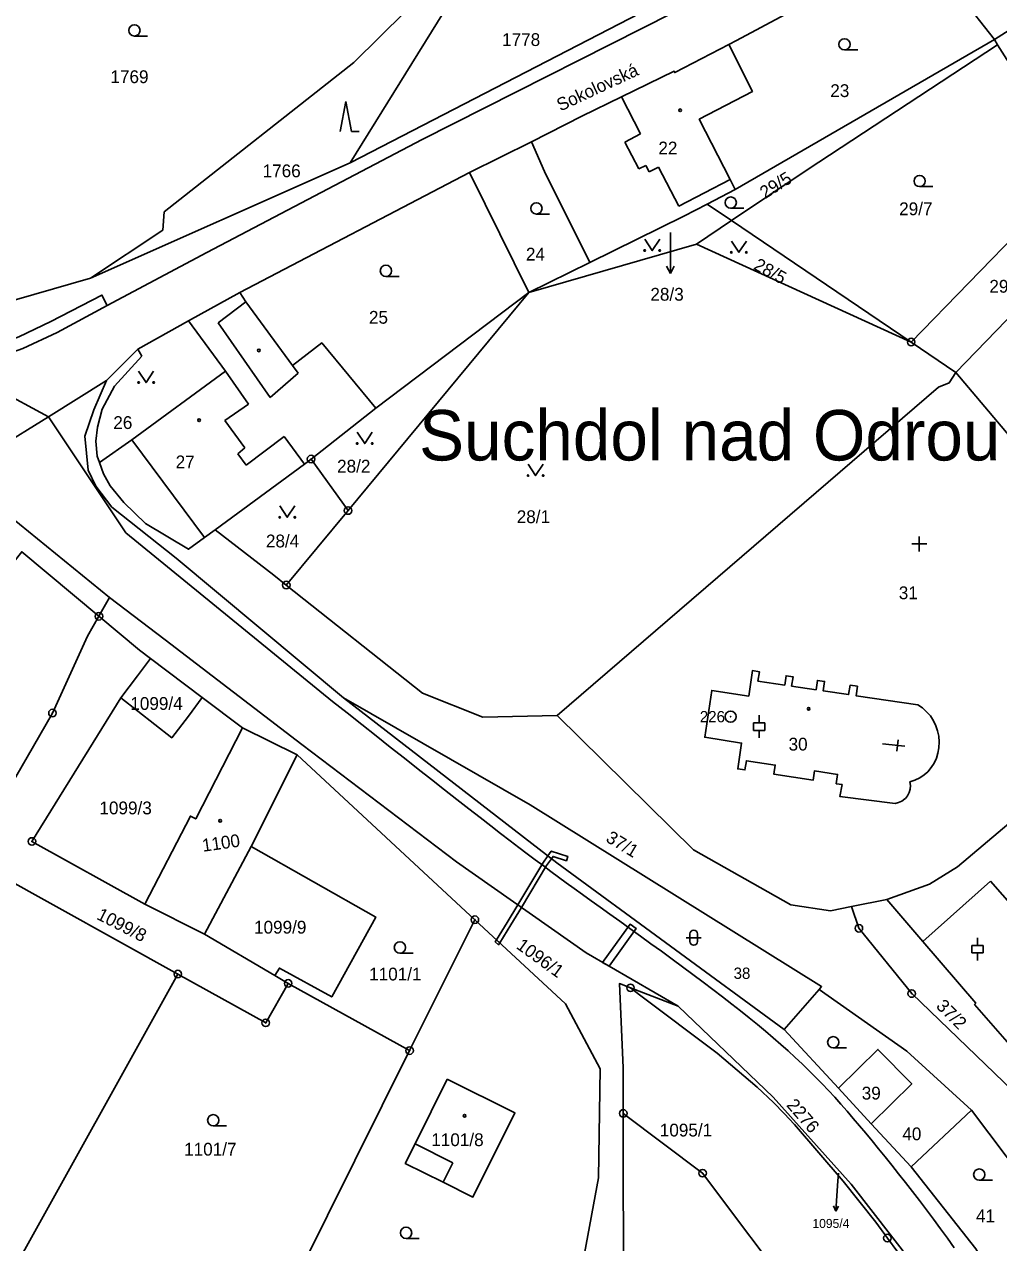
# Model space of a CAD drawing. Extents: x -504988 to -494607, y -1123820 to -1114018.
# Drawn here: x -497790.5 to -497661.1, y -1119332.3 to -1119170.5 of the extents above; entities that cross this region are included whole.
import ezdxf

# ---------------------------------------------------------------- set-up
doc = ezdxf.new("R2010")
doc.units = 0
for name, color, linetype in [('Hranice parcel', 7, 'Continuous'), ('Parcelní čísla', 7, 'Continuous'), ('Pop  PČ popisy', 7, 'Continuous'), ('Vnitřní kresba', 7, 'Continuous'), ('Věcná břemena k části', 7, 'Continuous'), ('Značky bodu BP', 7, 'Continuous'), ('Značky budov', 7, 'Continuous'), ('Značky kultur', 7, 'Continuous')]:
    doc.layers.add(name, color=color, linetype=linetype)

msp = doc.modelspace()

# ---------------------------------------------------------------- linework, layer by layer
at = {"layer": 'Hranice parcel'}
for p, q in [((-497661.69, -1119172.47), (-497620.57, -1119146.31)), ((-497696.9, -1119162.82), (-497747.25, -1119188.87)), ((-497668.67, -1119163.56), (-497661.69, -1119172.47)), ((-497747.25, -1119188.87), (-497734.84, -1119168.91)), ((-497696.1, -1119192.42), (-497661.69, -1119172.47)), ((-497661.69, -1119172.47), (-497661.25, -1119173.18)), ((-497723.18, -1119186.07), (-497731.4, -1119190.16)), ((-497747.25, -1119188.87), (-497781.75, -1119204.19)), ((-497761.89, -1119206.09), (-497731.4, -1119190.16)), ((-497651.17, -1119190.47), (-497672.74, -1119212.67)), ((-497699.82, -1119194.35), (-497696.1, -1119192.42)), ((-497696.58, -1119196.54), (-497699.82, -1119194.35)), ((-497701.23, -1119199.67), (-497696.58, -1119196.54)), ((-497696.58, -1119196.54), (-497672.74, -1119212.67)), ((-497701.23, -1119199.67), (-497723.5, -1119206.09)), ((-497672.74, -1119212.67), (-497701.23, -1119199.67)), ((-497650.53, -1119199.84), (-497666.81, -1119216.69)), ((-497723.5, -1119206.09), (-497715.43, -1119202.11)), ((-497781.75, -1119204.19), (-497796.95, -1119208.58)), ((-497768.72, -1119209.86), (-497761.89, -1119206.09)), ((-497723.5, -1119206.09), (-497747.52, -1119235.04)), ((-497743.85, -1119221.44), (-497723.5, -1119206.09)), ((-497775.46, -1119213.63), (-497768.72, -1119209.86)), ((-497666.81, -1119216.69), (-497672.74, -1119212.67)), ((-497779.6, -1119217.79), (-497775.46, -1119213.63)), ((-497775.46, -1119213.63), (-497774.9, -1119214.56)), ((-497801.27, -1119215.06), (-497787.31, -1119222.58)), ((-497779.6, -1119217.79), (-497787.31, -1119222.58)), ((-497666.81, -1119216.69), (-497635.22, -1119254.15)), ((-497787.31, -1119222.58), (-497799.78, -1119230.32)), ((-497752.44, -1119228.2), (-497743.85, -1119221.44)), ((-497752.44, -1119228.2), (-497747.52, -1119235.04)), ((-497747.52, -1119235.04), (-497755.73, -1119244.93)), ((-497779.21, -1119246.57), (-497780.61, -1119249.08)), ((-497780.61, -1119249.08), (-497775.2, -1119253.6)), ((-497773.75, -1119254.69), (-497775.49, -1119257)), ((-497775.2, -1119253.6), (-497773.75, -1119254.69)), ((-497773.75, -1119254.69), (-497766.89, -1119259.86)), ((-497775.49, -1119257), (-497777.71, -1119259.91)), ((-497777.71, -1119259.91), (-497789.5, -1119278.98)), ((-497766.89, -1119259.86), (-497768.71, -1119262.36)), ((-497766.89, -1119259.86), (-497761.54, -1119263.88)), ((-497797.87, -1119281.19), (-497786.78, -1119261.93)), ((-497761.54, -1119263.88), (-497754.3, -1119267.48)), ((-497760.37, -1119279.65), (-497754.3, -1119267.48)), ((-497754.3, -1119267.48), (-497730.68, -1119289.37)), ((-497789.5, -1119278.98), (-497774.53, -1119287.3)), ((-497766.59, -1119291.29), (-497760.37, -1119279.65)), ((-497797.87, -1119281.19), (-497770.13, -1119296.59)), ((-497766.59, -1119291.29), (-497774.53, -1119287.3)), ((-497680.67, -1119287.64), (-497675.97, -1119286.71)), ((-497679.68, -1119290.51), (-497680.67, -1119287.64)), ((-497739.35, -1119306.76), (-497730.68, -1119289.37)), ((-497757.24, -1119296.8), (-497766.59, -1119291.29)), ((-497792.3, -1119336.49), (-497770.13, -1119296.59)), ((-497755.48, -1119297.83), (-497757.24, -1119296.8)), ((-497755.48, -1119297.83), (-497739.35, -1119306.76)), ((-497710.01, -1119298.42), (-497703.68, -1119300.86)), ((-497689.62, -1119303.95), (-497684.95, -1119298.63)), ((-497682.38, -1119311.76), (-497689.62, -1119303.95)), ((-497739.35, -1119306.76), (-497757.24, -1119342.64)), ((-497678.04, -1119316.46), (-497682.38, -1119311.76)), ((-497672.73, -1119322.19), (-497664.73, -1119314.68)), ((-497672.73, -1119322.19), (-497678.04, -1119316.46))]:
    msp.add_line(p, q, dxfattribs=at)
for points in [[(-497729.61, -1119158.59), (-497746.77, -1119175.56), (-497771.93, -1119195.38), (-497772.14, -1119197.79), (-497781.75, -1119204.19)], [(-497696.97, -1119173.16), (-497695.94, -1119172.63), (-497671.31, -1119159.42)], [(-497696.97, -1119173.16), (-497704.13, -1119176.88), (-497704.23, -1119176.68), (-497711.22, -1119180.12), (-497716.49, -1119182.66), (-497723.18, -1119186.07)], [(-497696.1, -1119192.42), (-497696.78, -1119191.09), (-497700.87, -1119183.07), (-497693.82, -1119179.38), (-497696.97, -1119173.16)], [(-497696.58, -1119196.54), (-497686.55, -1119189.79), (-497661.25, -1119173.18)], [(-497661.25, -1119173.18), (-497659.42, -1119176.11), (-497653.87, -1119184.57)], [(-497723.18, -1119186.07), (-497721.43, -1119190.02), (-497715.43, -1119202.11)], [(-497731.4, -1119190.16), (-497729.33, -1119194.34), (-497723.5, -1119206.09)], [(-497715.43, -1119202.11), (-497702.93, -1119195.96), (-497699.82, -1119194.35)], [(-497804.87, -1119212.64), (-497800.83, -1119213.46), (-497796.59, -1119213.64), (-497794.65, -1119213.21), (-497791.26, -1119211.96), (-497786.99, -1119209.93), (-497780.21, -1119206.43), (-497779.52, -1119207.83), (-497786.17, -1119211.39), (-497790.7, -1119213.51), (-497794.49, -1119214.85), (-497796.86, -1119215.32), (-497801.27, -1119215.06)], [(-497761.89, -1119206.09), (-497761.08, -1119207.32), (-497754.88, -1119215.77), (-497751.02, -1119212.79), (-497743.85, -1119221.44)], [(-497780.54, -1119228.65), (-497776.22, -1119225.67), (-497763.82, -1119216.52), (-497768.72, -1119209.86)], [(-497774.9, -1119214.56), (-497778.53, -1119218.52), (-497780.16, -1119221.56), (-497780.8, -1119223.96), (-497781, -1119225.81), (-497780.83, -1119227.8), (-497780.54, -1119228.65)], [(-497748.12, -1119259.92), (-497770.37, -1119241.35), (-497778.89, -1119234.61), (-497781.02, -1119231.78), (-497782.03, -1119229.68), (-497782.49, -1119225.17), (-497781.28, -1119221.65), (-497779.6, -1119217.79)], [(-497666.81, -1119216.69), (-497667.68, -1119218.08), (-497669.09, -1119218.66), (-497719.75, -1119262.25)], [(-497780.54, -1119228.65), (-497780.02, -1119230.16), (-497779.11, -1119231.75), (-497777.31, -1119233.95), (-497774.43, -1119236.78)], [(-497765.18, -1119237.58), (-497753.32, -1119228.89), (-497752.44, -1119228.2)], [(-497779.21, -1119246.57), (-497798.37, -1119230.99), (-497799.78, -1119230.32)], [(-497774.43, -1119236.78), (-497768.73, -1119240.17), (-497766.61, -1119238.63), (-497765.18, -1119237.58)], [(-497765.18, -1119237.58), (-497757.37, -1119243.63), (-497755.73, -1119244.93)], [(-497792.88, -1119243.11), (-497790.85, -1119240.52), (-497780.61, -1119249.08)], [(-497755.73, -1119244.93), (-497737.62, -1119259.28), (-497729.63, -1119262.48), (-497719.75, -1119262.25)], [(-497703.68, -1119300.86), (-497715.92, -1119293.78), (-497733.1, -1119281.67), (-497753.67, -1119266.09), (-497771.83, -1119252.19), (-497779.21, -1119246.57)], [(-497786.78, -1119261.93), (-497782.11, -1119251.73), (-497780.61, -1119249.08)], [(-497671.87, -1119260.82), (-497680.06, -1119259.63), (-497679.88, -1119258.37), (-497680.86, -1119258.23), (-497681.05, -1119259.48), (-497684.42, -1119258.98), (-497684.24, -1119257.73), (-497685.18, -1119257.59), (-497685.36, -1119258.84), (-497688.61, -1119258.35), (-497688.42, -1119257.1), (-497689.35, -1119256.97), (-497689.53, -1119258.22), (-497693.09, -1119257.69), (-497692.9, -1119256.44), (-497693.83, -1119256.3), (-497694.3, -1119259.67), (-497699.22, -1119258.93), (-497700.16, -1119265.14), (-497695.26, -1119265.92), (-497695.77, -1119269.34), (-497694.81, -1119269.49), (-497694.62, -1119268.26), (-497690.79, -1119268.84), (-497690.97, -1119270.06), (-497685.76, -1119270.85), (-497685.58, -1119269.62), (-497682.51, -1119270.09), (-497682.69, -1119271.31), (-497681.92, -1119271.43), (-497682.19, -1119273.02), (-497674.87, -1119273.92)], [(-497768.71, -1119262.36), (-497770.94, -1119265.2), (-497777.71, -1119259.91)], [(-497684.95, -1119298.63), (-497684.63, -1119298.25), (-497723.32, -1119274.12), (-497748.12, -1119259.92)], [(-497689.62, -1119303.95), (-497719.78, -1119281.83), (-497748.12, -1119259.92)], [(-497674.87, -1119273.92), (-497674.4, -1119273.82), (-497673.97, -1119273.62), (-497673.58, -1119273.34), (-497673.51, -1119273.27), (-497673.21, -1119272.91), (-497672.99, -1119272.48), (-497672.86, -1119272.02), (-497672.84, -1119271.54), (-497672.91, -1119271.07), (-497672.23, -1119270.84), (-497671.59, -1119270.53), (-497671, -1119270.12), (-497670.54, -1119269.72), (-497670.08, -1119269.17), (-497669.69, -1119268.57), (-497669.39, -1119267.92), (-497669.19, -1119267.24), (-497669.08, -1119266.53), (-497669.03, -1119265.77), (-497669.08, -1119265.02), (-497669.23, -1119264.28), (-497669.44, -1119263.64), (-497669.77, -1119262.96), (-497670.18, -1119262.32), (-497670.68, -1119261.75), (-497671.24, -1119261.25), (-497671.87, -1119260.82)], [(-497719.75, -1119262.25), (-497701.66, -1119280.11), (-497688.73, -1119287.38), (-497683.43, -1119288.19), (-497680.67, -1119287.64)], [(-497774.53, -1119287.3), (-497768.45, -1119275.61), (-497767.74, -1119275.98), (-497761.54, -1119263.88)], [(-497675.97, -1119286.71), (-497670.32, -1119284.67), (-497666.59, -1119282.37), (-497653.77, -1119271.55)], [(-497760.37, -1119279.65), (-497743.84, -1119289.02), (-497749.68, -1119299.63), (-497756.63, -1119295.8), (-497757.24, -1119296.8)], [(-497675.97, -1119286.71), (-497671.2, -1119292.26), (-497664.15, -1119300.47), (-497664.32, -1119300.62), (-497656.56, -1119309.48)], [(-497730.68, -1119289.37), (-497718.64, -1119300.53), (-497714.03, -1119309.16), (-497714.28, -1119323.63), (-497716.11, -1119333.69)], [(-497657.98, -1119313.31), (-497672.67, -1119299.18), (-497679.68, -1119290.51)], [(-497770.13, -1119296.59), (-497758.46, -1119303.07), (-497755.48, -1119297.83)], [(-497710.97, -1119315.1), (-497710.97, -1119309.06), (-497711.49, -1119297.85), (-497710.01, -1119298.42)], [(-497673.13, -1119335.38), (-497675.9, -1119331.65), (-497677.44, -1119329.55), (-497681.75, -1119324.11), (-497688.24, -1119316.56), (-497689.6, -1119315.09), (-497691, -1119313.64), (-497693.17, -1119311.59), (-497698.48, -1119307.09), (-497708.8, -1119299.34), (-497710.01, -1119298.42)], [(-497664.73, -1119314.68), (-497673.3, -1119306.85), (-497684.95, -1119298.63)], [(-497703.68, -1119300.86), (-497691.05, -1119312.92), (-497680.71, -1119324.47), (-497672.56, -1119334.97)], [(-497678.04, -1119316.46), (-497672.67, -1119311.16), (-497677.16, -1119306.6), (-497682.38, -1119311.76)], [(-497734.34, -1119310.55), (-497725.37, -1119315.02), (-497730.95, -1119326.21), (-497734.9, -1119324.24), (-497739.92, -1119321.74), (-497738.63, -1119319.15), (-497734.34, -1119310.55)], [(-497653.7, -1119349.05), (-497655.52, -1119326.88), (-497664.73, -1119314.68)], [(-497704.45, -1119351.66), (-497710.95, -1119341.02), (-497710.97, -1119315.1)], [(-497710.97, -1119315.1), (-497700.43, -1119323.03), (-497687.74, -1119339.95)], [(-497653.7, -1119349.05), (-497655.81, -1119346.48), (-497664.15, -1119333.08), (-497672.73, -1119322.19)]]:
    msp.add_lwpolyline(points, dxfattribs=at)
at = {"layer": 'Pop  PČ popisy'}
for p, q in [((-497704.72, -1119198.1), (-497704.72, -1119200.57)), ((-497704.72, -1119200.57), (-497704.72, -1119203.57)), ((-497704.72, -1119203.57), (-497705.22, -1119202.57)), ((-497704.72, -1119203.57), (-497704.22, -1119202.57)), ((-497682.61, -1119326.06), (-497682.75, -1119328.07)), ((-497682.75, -1119328.07), (-497683.04, -1119327.37)), ((-497682.75, -1119328.07), (-497682.37, -1119327.42))]:
    msp.add_line(p, q, dxfattribs=at)
msp.add_lwpolyline([(-497682.38, -1119323.01), (-497682.46, -1119324.06), (-497682.61, -1119326.06)], dxfattribs=at)
at = {"layer": 'Vnitřní kresba'}
for p, q in [((-497737.69, -1119185.78), (-497695.99, -1119164.68)), ((-497708.69, -1119185), (-497711.22, -1119180.12)), ((-497710.76, -1119186.1), (-497708.69, -1119185)), ((-497766.26, -1119200.77), (-497737.69, -1119185.78)), ((-497708.9, -1119189.68), (-497710.76, -1119186.1)), ((-497707.96, -1119189.21), (-497708.9, -1119189.68)), ((-497707.52, -1119190.06), (-497707.96, -1119189.21)), ((-497706.3, -1119189.43), (-497707.52, -1119190.06)), ((-497703.61, -1119194.63), (-497706.3, -1119189.43)), ((-497696.78, -1119191.09), (-497703.61, -1119194.63)), ((-497779.52, -1119207.83), (-497766.26, -1119200.77)), ((-497764.78, -1119210.1), (-497761.08, -1119207.32)), ((-497757.85, -1119220.02), (-497764.78, -1119210.1)), ((-497754.88, -1119215.77), (-497754.14, -1119216.78)), ((-497763.82, -1119216.52), (-497760.76, -1119220.92)), ((-497754.14, -1119216.78), (-497757.85, -1119220.02)), ((-497760.76, -1119220.92), (-497763.87, -1119223.08)), ((-497777.03, -1119237.99), (-497787.31, -1119222.58)), ((-497763.87, -1119223.08), (-497761.21, -1119226.72)), ((-497766.61, -1119238.63), (-497776.22, -1119225.67)), ((-497761.06, -1119229), (-497756, -1119225.2)), ((-497756, -1119225.2), (-497753.32, -1119228.89)), ((-497761.21, -1119226.72), (-497762.16, -1119227.53)), ((-497762.16, -1119227.53), (-497761.06, -1119229)), ((-497749.59, -1119260.38), (-497777.03, -1119237.99)), ((-497671.2, -1119292.26), (-497662.21, -1119284.26)), ((-497662.21, -1119284.26), (-497655.04, -1119292.44)), ((-497733.61, -1119321.65), (-497738.63, -1119319.15)), ((-497734.9, -1119324.24), (-497733.61, -1119321.65))]:
    msp.add_line(p, q, dxfattribs=at)
msp.add_lwpolyline([(-497667.01, -1119332.96), (-497667.92, -1119331.68), (-497668.85, -1119330.42), (-497669.78, -1119329.15), (-497670.72, -1119327.9), (-497671.65, -1119326.68), (-497672.58, -1119325.46), (-497673.5, -1119324.28), (-497674.41, -1119323.12), (-497675.32, -1119321.97), (-497676.2, -1119320.87), (-497677.06, -1119319.8), (-497677.92, -1119318.74), (-497678.76, -1119317.72), (-497679.59, -1119316.73), (-497680.42, -1119315.75), (-497681.24, -1119314.8), (-497682.06, -1119313.86), (-497682.89, -1119312.94), (-497683.73, -1119312.04), (-497684.57, -1119311.15), (-497685.44, -1119310.26), (-497686.31, -1119309.39), (-497687.2, -1119308.53), (-497688.13, -1119307.65), (-497689.07, -1119306.79), (-497690.04, -1119305.93), (-497691.05, -1119305.05), (-497692.08, -1119304.18), (-497693.14, -1119303.3), (-497694.25, -1119302.4), (-497695.39, -1119301.49), (-497696.56, -1119300.57), (-497697.8, -1119299.61), (-497699.06, -1119298.65), (-497700.37, -1119297.66), (-497701.73, -1119296.65), (-497703.1, -1119295.63), (-497704.49, -1119294.61), (-497705.91, -1119293.57), (-497707.31, -1119292.56), (-497708.7, -1119291.55), (-497710.09, -1119290.55), (-497711.44, -1119289.58), (-497712.75, -1119288.64), (-497714.02, -1119287.72), (-497715.23, -1119286.85), (-497716.38, -1119286.02), (-497717.48, -1119285.22), (-497718.54, -1119284.46), (-497719.57, -1119283.71), (-497720.6, -1119282.95), (-497721.62, -1119282.19), (-497722.66, -1119281.42), (-497723.74, -1119280.61), (-497724.84, -1119279.77), (-497726.01, -1119278.88), (-497727.26, -1119277.93), (-497728.57, -1119276.91), (-497729.98, -1119275.82), (-497731.49, -1119274.64), (-497733.07, -1119273.41), (-497734.71, -1119272.12), (-497736.45, -1119270.76), (-497738.21, -1119269.36), (-497740.03, -1119267.93), (-497741.91, -1119266.45), (-497743.79, -1119264.96), (-497745.7, -1119263.45), (-497747.66, -1119261.91), (-497749.59, -1119260.38)], dxfattribs=at)
at = {"layer": 'Věcná břemena k části'}
for points in [[(-497724.5, -1119287.73), (-497721.15, -1119282.17), (-497720.51, -1119281.27), (-497720.98, -1119280.9), (-497721.65, -1119281.85), (-497724.99, -1119287.39)], [(-497720.98, -1119280.9), (-497720.51, -1119281.27), (-497720.29, -1119280.96), (-497718.52, -1119281.54), (-497718.34, -1119280.97), (-497720.53, -1119280.26)], [(-497727.81, -1119292.03), (-497727.37, -1119292.44), (-497725.9, -1119290.04), (-497724.5, -1119287.73), (-497724.99, -1119287.39), (-497726.41, -1119289.73)], [(-497712.85, -1119295.56), (-497709.24, -1119290.56), (-497710.06, -1119289.98), (-497713.72, -1119295.05)], [(-497727.81, -1119292.03), (-497727.98, -1119292.3), (-497727.54, -1119292.7), (-497727.37, -1119292.44)]]:
    msp.add_lwpolyline(points, close=True, dxfattribs=at)
at = {"layer": 'Značky bodu BP'}
for centre, radius in [((-497672.74, -1119212.67), 0.5), ((-497672.74, -1119212.67), 0.0303), ((-497752.44, -1119228.2), 0.5), ((-497752.44, -1119228.2), 0.0303), ((-497747.52, -1119235.04), 0.5), ((-497747.52, -1119235.04), 0.0303), ((-497755.73, -1119244.93), 0.5), ((-497755.73, -1119244.93), 0.0303), ((-497780.61, -1119249.08), 0.5), ((-497780.61, -1119249.08), 0.0303), ((-497786.78, -1119261.93), 0.5), ((-497786.78, -1119261.93), 0.0303), ((-497696.71, -1119262.41), 0.75), ((-497696.71, -1119262.41), 0.03), ((-497789.5, -1119278.98), 0.5), ((-497789.5, -1119278.98), 0.0303), ((-497730.68, -1119289.37), 0.5), ((-497730.68, -1119289.37), 0.0303), ((-497679.68, -1119290.51), 0.5), ((-497679.68, -1119290.51), 0.0303), ((-497770.13, -1119296.59), 0.5), ((-497770.13, -1119296.59), 0.0303), ((-497755.48, -1119297.83), 0.5), ((-497755.48, -1119297.83), 0.0303), ((-497710.01, -1119298.42), 0.5), ((-497710.01, -1119298.42), 0.0303), ((-497672.67, -1119299.18), 0.5), ((-497672.67, -1119299.18), 0.0303), ((-497758.46, -1119303.07), 0.5), ((-497758.46, -1119303.07), 0.0303), ((-497739.35, -1119306.76), 0.5), ((-497739.35, -1119306.76), 0.0303), ((-497710.97, -1119315.1), 0.5), ((-497710.97, -1119315.1), 0.0303), ((-497700.43, -1119323.03), 0.5), ((-497700.43, -1119323.03), 0.0303), ((-497675.9, -1119331.65), 0.5), ((-497675.9, -1119331.65), 0.0303)]:
    msp.add_circle(centre, radius, dxfattribs=at)
at = {"layer": 'Značky budov'}
for p, q in [((-497673.57, -1119266.33), (-497676.55, -1119266.02)), ((-497674.48, -1119265.48), (-497674.64, -1119266.98))]:
    msp.add_line(p, q, dxfattribs=at)
for centre in [(-497703.42, -1119181.89), (-497759.36, -1119213.77), (-497767.31, -1119223.04), (-497686.35, -1119261.38), (-497764.5, -1119276.23), (-497732.04, -1119315.41)]:
    msp.add_circle(centre, 0.175, dxfattribs=at)
at = {"layer": 'Značky kultur'}
for p, q in [((-497775.9, -1119172.03), (-497774.15, -1119172.03)), ((-497681.59, -1119173.88), (-497679.84, -1119173.88)), ((-497747.8, -1119180.72), (-497748.55, -1119184.72)), ((-497747.05, -1119184.72), (-497747.8, -1119180.72)), ((-497747.05, -1119184.72), (-497746.05, -1119184.72)), ((-497671.61, -1119192.03), (-497669.86, -1119192.03)), ((-497696.7, -1119194.89), (-497694.95, -1119194.89)), ((-497722.51, -1119195.67), (-497720.76, -1119195.67)), ((-497742.5, -1119203.96), (-497740.75, -1119203.96)), ((-497671.66, -1119240.47), (-497671.66, -1119238.47)), ((-497670.66, -1119239.47), (-497672.66, -1119239.47)), ((-497692.94, -1119263.23), (-497692.94, -1119262.23)), ((-497693.69, -1119263.23), (-497692.19, -1119263.23)), ((-497693.69, -1119264.23), (-497693.69, -1119263.23)), ((-497693.69, -1119264.23), (-497692.19, -1119264.23)), ((-497692.94, -1119265.23), (-497692.94, -1119264.23)), ((-497692.19, -1119264.23), (-497692.19, -1119263.23)), ((-497702.61, -1119291.77), (-497700.61, -1119291.77)), ((-497702.11, -1119291.27), (-497702.11, -1119292.27)), ((-497701.11, -1119292.27), (-497701.11, -1119291.27)), ((-497663.94, -1119292.79), (-497663.94, -1119291.79)), ((-497740.64, -1119293.81), (-497738.89, -1119293.81)), ((-497664.69, -1119292.79), (-497663.19, -1119292.79)), ((-497664.69, -1119293.79), (-497664.69, -1119292.79)), ((-497664.69, -1119293.79), (-497663.19, -1119293.79)), ((-497663.94, -1119294.79), (-497663.94, -1119293.79)), ((-497663.19, -1119293.79), (-497663.19, -1119292.79)), ((-497683.09, -1119306.4), (-497681.34, -1119306.4)), ((-497765.42, -1119316.75), (-497763.67, -1119316.75)), ((-497663.7, -1119323.97), (-497661.95, -1119323.97)), ((-497739.82, -1119331.7), (-497738.07, -1119331.7))]:
    msp.add_line(p, q, dxfattribs=at)
for points in [[(-497708.13, -1119199.01), (-497707.13, -1119200.51), (-497706.13, -1119199.01)], [(-497696.62, -1119199.25), (-497695.62, -1119200.75), (-497694.62, -1119199.25)], [(-497775.34, -1119216.54), (-497774.34, -1119218.04), (-497773.34, -1119216.54)], [(-497746.31, -1119224.64), (-497745.31, -1119226.14), (-497744.31, -1119224.64)], [(-497723.61, -1119228.89), (-497722.61, -1119230.39), (-497721.61, -1119228.89)], [(-497756.59, -1119234.43), (-497755.59, -1119235.93), (-497754.59, -1119234.43)]]:
    msp.add_lwpolyline(points, dxfattribs=at)
for centre, radius in [((-497775.9, -1119171.28), 0.75), ((-497681.59, -1119173.13), 0.75), ((-497671.61, -1119191.28), 0.75), ((-497696.7, -1119194.14), 0.75), ((-497722.51, -1119194.92), 0.75), ((-497708.13, -1119200.51), 0.1), ((-497706.13, -1119200.51), 0.1), ((-497696.62, -1119200.75), 0.1), ((-497694.62, -1119200.75), 0.1), ((-497742.5, -1119203.21), 0.75), ((-497775.34, -1119218.04), 0.1), ((-497773.34, -1119218.04), 0.1), ((-497746.31, -1119226.14), 0.1), ((-497744.31, -1119226.14), 0.1), ((-497723.61, -1119230.39), 0.1), ((-497721.61, -1119230.39), 0.1), ((-497756.59, -1119235.93), 0.1), ((-497754.59, -1119235.93), 0.1), ((-497740.64, -1119293.06), 0.75), ((-497683.09, -1119305.65), 0.75), ((-497765.42, -1119316), 0.75), ((-497663.7, -1119323.22), 0.75), ((-497739.82, -1119330.95), 0.75)]:
    msp.add_circle(centre, radius, dxfattribs=at)
for centre, start, end in [((-497701.61, -1119291.27), 0, 180), ((-497701.61, -1119292.27), 180, 359.9879)]:
    msp.add_arc(centre, 0.5, start, end, dxfattribs=at)

# ---------------------------------------------------------------- texts
at = {"layer": 'Parcelní čísla'}
for s, height, p in [('1778', 1.7, (-497727.06, -1119173.35)), ('1769', 1.7, (-497779.08, -1119178.28)), ('23', 1.7, (-497683.48, -1119180.13)), ('22', 1.7, (-497706.31, -1119187.75)), ('1766', 1.7, (-497758.87, -1119190.78)), ('29/7', 1.7, (-497674.33, -1119195.82)), ('24', 1.7, (-497723.9, -1119201.84)), ('29/4', 1.7, (-497662.35, -1119206.11)), ('28/3', 1.7, (-497707.37, -1119207.17)), ('25', 1.7, (-497744.75, -1119210.23)), ('26', 1.7, (-497778.7, -1119224.21)), ('27', 1.7, (-497770.42, -1119229.43)), ('28/2', 1.7, (-497748.98, -1119230)), ('28/1', 1.7, (-497725.12, -1119236.71)), ('28/4', 1.7, (-497758.43, -1119239.93)), ('31', 1.7, (-497674.38, -1119246.81)), ('1099/4', 1.7, (-497776.44, -1119261.51)), ('30', 1.7, (-497689.02, -1119266.91)), ('1099/3', 1.7, (-497780.54, -1119275.38)), ('1099/9', 1.7, (-497760.01, -1119291.22)), ('1101/1', 1.7, (-497744.72, -1119297.44)), ('38', 1.5, (-497696.32, -1119297.23)), ('39', 1.7, (-497679.3, -1119313.25)), ('1095/1', 1.7, (-497706.12, -1119318.16)), ('1101/8', 1.7, (-497736.47, -1119319.44)), ('40', 1.7, (-497673.91, -1119318.66)), ('1101/7', 1.7, (-497769.29, -1119320.7)), ('41', 1.7, (-497664.13, -1119329.55)), ('1095/4', 1.2, (-497685.85, -1119330.31))]:
    msp.add_text(s, height=height, dxfattribs=at).set_placement(p)
for s, rotation, p in [('29/5', 32, (-497692.16, -1119193.72)), ('28/5', 331, (-497693.79, -1119202.91)), ('37/1', 329, (-497713.41, -1119278.92)), ('1100', 8, (-497766.79, -1119280.36)), ('1099/8', 333, (-497781.04, -1119289.23)), ('1096/1', 324, (-497725.3, -1119293.09)), ('37/2', 315, (-497669.53, -1119300.96)), ('2276', 311, (-497689.39, -1119314.04))]:
    msp.add_text(s, height=1.7, rotation=rotation, dxfattribs=at).set_placement(p)
at = {"layer": 'Pop  PČ popisy'}
msp.add_text('Sokolovská', height=1.7, rotation=25, dxfattribs=at).set_placement((-497719.32, -1119182.06))
msp.add_text('Suchdol nad Odrou', height=6.7, dxfattribs=at).set_placement((-497738.09, -1119228.39))
at = {"layer": 'Značky bodu BP'}
msp.add_text('226', height=1.5, dxfattribs=at).set_placement((-497700.81, -1119263.16))

doc.saveas('drawing.dxf')
